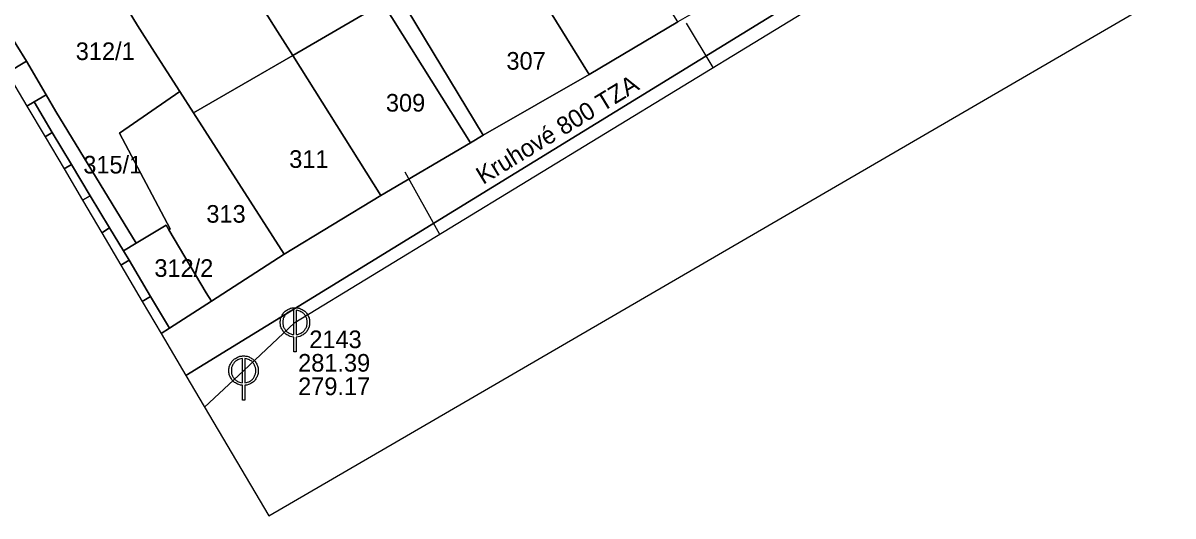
# Model space of a CAD drawing. Extents: x -571312 to -571060, y -1087128 to -1086933.
# Drawn here: x -571251.9 to -571153.9, y -1087127.5 to -1087085.5 of the extents above; entities that cross this region are included whole.
import ezdxf

# ---------------------------------------------------------------- set-up
doc = ezdxf.new("R2010")
doc.units = 0
for name, color, linetype in [('Default', 7, 'Continuous'), ('Kanalizační přípojka', 7, 'Continuous'), ('Kanalizační stoka', 7, 'Continuous'), ('Kanalizační šachta', 7, 'Continuous'), ('Parcela-polygon', 7, 'Continuous'), ('Parcela-text', 7, 'Continuous'), ('Popis kmenové stoky', 7, 'Continuous'), ('Popis šachty', 7, 'Continuous')]:
    doc.layers.add(name, color=color, linetype=linetype)

msp = doc.modelspace()

# ---------------------------------------------------------------- linework, layer by layer
at = {"layer": 'Default'}
for points in [[(-571228.863, -1087112.288), (-571229.121, -1087112.27), (-571229.383, -1087112.124), (-571229.68, -1087111.96), (-571229.845, -1087111.663), (-571230.01, -1087111.365), (-571230.01, -1087111.04), (-571230.01, -1087110.713), (-571229.842, -1087110.413), (-571229.673, -1087110.112), (-571229.375, -1087109.951), (-571229.077, -1087109.79), (-571228.76, -1087109.79), (-571228.445, -1087109.79), (-571228.146, -1087109.951), (-571227.847, -1087110.112), (-571227.678, -1087110.413), (-571227.51, -1087110.713), (-571227.51, -1087111.04), (-571227.51, -1087111.365), (-571227.675, -1087111.663), (-571227.84, -1087111.96), (-571228.137, -1087112.124), (-571228.399, -1087112.27), (-571228.657, -1087112.288)], [(-571228.863, -1087110.002), (-571229.06, -1087110.019), (-571229.275, -1087110.134), (-571229.524, -1087110.269), (-571229.663, -1087110.519), (-571229.802, -1087110.769), (-571229.802, -1087111.04), (-571229.802, -1087111.311), (-571229.666, -1087111.558), (-571229.529, -1087111.804), (-571229.28, -1087111.941), (-571229.068, -1087112.061), (-571228.863, -1087112.075)], [(-571228.657, -1087112.075), (-571228.452, -1087112.061), (-571228.238, -1087111.941), (-571227.991, -1087111.804), (-571227.854, -1087111.558), (-571227.718, -1087111.311), (-571227.718, -1087111.04), (-571227.718, -1087110.769), (-571227.858, -1087110.519), (-571227.998, -1087110.269), (-571228.247, -1087110.134), (-571228.46, -1087110.019), (-571228.657, -1087110.002)], [(-571233.243, -1087116.398), (-571233.501, -1087116.38), (-571233.763, -1087116.234), (-571234.06, -1087116.07), (-571234.225, -1087115.773), (-571234.39, -1087115.475), (-571234.39, -1087115.15), (-571234.39, -1087114.823), (-571234.222, -1087114.523), (-571234.053, -1087114.222), (-571233.755, -1087114.061), (-571233.457, -1087113.9), (-571233.14, -1087113.9), (-571232.825, -1087113.9), (-571232.526, -1087114.061), (-571232.227, -1087114.222), (-571232.058, -1087114.523), (-571231.89, -1087114.823), (-571231.89, -1087115.15), (-571231.89, -1087115.475), (-571232.055, -1087115.773), (-571232.22, -1087116.07), (-571232.517, -1087116.234), (-571232.779, -1087116.38), (-571233.037, -1087116.398)], [(-571233.243, -1087114.112), (-571233.44, -1087114.129), (-571233.655, -1087114.244), (-571233.904, -1087114.379), (-571234.043, -1087114.629), (-571234.182, -1087114.879), (-571234.182, -1087115.15), (-571234.182, -1087115.421), (-571234.046, -1087115.668), (-571233.909, -1087115.914), (-571233.66, -1087116.051), (-571233.448, -1087116.171), (-571233.243, -1087116.185)], [(-571233.037, -1087116.185), (-571232.832, -1087116.171), (-571232.618, -1087116.051), (-571232.371, -1087115.914), (-571232.234, -1087115.668), (-571232.098, -1087115.421), (-571232.098, -1087115.15), (-571232.098, -1087114.879), (-571232.238, -1087114.629), (-571232.378, -1087114.379), (-571232.627, -1087114.244), (-571232.84, -1087114.129), (-571233.037, -1087114.112)]]:
    msp.add_open_spline(points, degree=3, dxfattribs=at)
at = {"layer": 'Kanalizační přípojka'}
for points in [[(-571195.42, -1087085.56), (-571193.154, -1087089.349)], [(-571219.41, -1087098.23), (-571216.438, -1087103.534)]]:
    msp.add_lwpolyline(points, dxfattribs=at)
at = {"layer": 'Kanalizační stoka'}
for points in [[(-571228.76, -1087111.04), (-571202.29, -1087094.915), (-571175.82, -1087078.79), (-571170.61, -1087076.5)], [(-571233.14, -1087115.15), (-571228.76, -1087111.04)], [(-571236.459, -1087118.265), (-571233.14, -1087115.15)]]:
    msp.add_lwpolyline(points, dxfattribs=at)
at = {"layer": 'Kanalizační šachta'}
for points in [[(-571228.863, -1087112.075), (-571228.863, -1087110.002)], [(-571228.657, -1087110.002), (-571228.657, -1087112.075)], [(-571228.657, -1087112.288), (-571228.657, -1087113.54), (-571228.863, -1087113.54), (-571228.863, -1087112.288)], [(-571233.243, -1087116.185), (-571233.243, -1087114.112)], [(-571233.037, -1087114.112), (-571233.037, -1087116.185)], [(-571233.037, -1087116.398), (-571233.037, -1087117.65), (-571233.243, -1087117.65), (-571233.243, -1087116.398)]]:
    msp.add_lwpolyline(points, dxfattribs=at)
at = {"layer": 'Parcela-polygon'}
for p, q in [((-571253.275, -1087089.78), (-571251.598, -1087092.62)), ((-571251.598, -1087092.62), (-571250.05, -1087095.242)), ((-571250.05, -1087095.242), (-571248.437, -1087097.976)), ((-571248.437, -1087097.976), (-571246.865, -1087100.637)), ((-571246.865, -1087100.637), (-571245.233, -1087103.403)), ((-571245.233, -1087103.403), (-571243.6, -1087106.169)), ((-571243.6, -1087106.169), (-571241.775, -1087109.26)), ((-571241.775, -1087109.26), (-571240.174, -1087111.972)), ((-571240.174, -1087111.972), (-571238.048, -1087115.573))]:
    msp.add_line(p, q, dxfattribs=at)
for points in [[(-571238.048, -1087115.573), (-571084.13, -1087021.07)], [(-571100.979, -1087051.983), (-571102.73, -1087043.67), (-571081.09, -1087028.01), (-571079.74, -1087027.03), (-571084.13, -1087021.07), (-571238.048, -1087115.573)], [(-571152.72, -1087058.97), (-571161.7, -1087064.52), (-571167.4, -1087067.96), (-571170.47, -1087067.33), (-571180.9, -1087049.87), (-571182.46, -1087047.26), (-571184.97, -1087043.06), (-571189.72, -1087045.85), (-571190.56, -1087046.39), (-571185.69, -1087054.37), (-571182.17, -1087060.4), (-571174.89, -1087072.57), (-571185.7, -1087079.22), (-571194.74, -1087084.64), (-571196.13, -1087085.46), (-571203.69, -1087089.94), (-571212.71, -1087095.11), (-571213.81, -1087095.76), (-571221.44, -1087100.23), (-571229.69, -1087105.23), (-571235.88, -1087109.23), (-571239.44, -1087111.53), (-571240.174, -1087111.972)], [(-571238.048, -1087115.573), (-571230.994, -1087127.523), (-571100.979, -1087051.983)], [(-571253.275, -1087089.78), (-571251.65, -1087088.8), (-571253.39, -1087085.95), (-571254.973, -1087086.903)], [(-571251.598, -1087092.62), (-571250.99, -1087092.27), (-571249.96, -1087091.66), (-571251.65, -1087088.8), (-571253.275, -1087089.78)], [(-571250.05, -1087095.242), (-571249.45, -1087094.88), (-571250.99, -1087092.27), (-571251.598, -1087092.62)], [(-571248.437, -1087097.976), (-571247.81, -1087097.6), (-571249.45, -1087094.88), (-571250.05, -1087095.242)], [(-571246.865, -1087100.637), (-571246.22, -1087100.25), (-571247.81, -1087097.6), (-571248.437, -1087097.976)], [(-571245.233, -1087103.403), (-571244.56, -1087103), (-571246.22, -1087100.25), (-571246.865, -1087100.637)], [(-571243.6, -1087106.169), (-571242.9, -1087105.75), (-571243.38, -1087104.94), (-571244.56, -1087103), (-571245.233, -1087103.403)], [(-571241.775, -1087109.26), (-571241.06, -1087108.83), (-571242.9, -1087105.75), (-571243.6, -1087106.169)], [(-571240.174, -1087111.972), (-571239.44, -1087111.53), (-571239.96, -1087110.68), (-571241.06, -1087108.83), (-571241.775, -1087109.26)]]:
    msp.add_lwpolyline(points, dxfattribs=at)
for points in [[(-571228.73, -1087069.23), (-571237.74, -1087074.6), (-571233.74, -1087080.71), (-571230.24, -1087086.27), (-571228.95, -1087088.31), (-571221.28, -1087083.87), (-571213.81, -1087095.76), (-571212.71, -1087095.11), (-571222.73, -1087078.55), (-571224.67, -1087075.35)], [(-571205.73, -1087074.32), (-571209.1, -1087076.39), (-571208.46, -1087077.42), (-571210.64, -1087078.7), (-571210.13, -1087079.52), (-571203.69, -1087089.94), (-571196.13, -1087085.46), (-571200.02, -1087079.25), (-571204.26, -1087072.46), (-571206.54, -1087072.99)], [(-571230.24, -1087086.27), (-571233.74, -1087080.71), (-571237.74, -1087074.6), (-571245.94, -1087079.58), (-571242.19, -1087085.75), (-571240.73, -1087088.03), (-571238.58, -1087091.38), (-571237.41, -1087093.2), (-571228.95, -1087088.31)], [(-571203.69, -1087089.94), (-571210.13, -1087079.52), (-571210.53, -1087081.27), (-571213.1, -1087082.94), (-571214.96, -1087082.48), (-571218.81, -1087076.21), (-571222.73, -1087078.55), (-571212.71, -1087095.11)], [(-571254.21, -1087084.57), (-571253.39, -1087085.95), (-571251.65, -1087088.8), (-571249.96, -1087091.66), (-571249.14, -1087093.07), (-571242.3, -1087104.3), (-571239.74, -1087102.77), (-571239.52, -1087103.15), (-571239.41, -1087103.08), (-571243.72, -1087094.92), (-571238.58, -1087091.38), (-571240.73, -1087088.03), (-571242.19, -1087085.75), (-571245.94, -1087079.58)], [(-571228.95, -1087088.31), (-571221.44, -1087100.23), (-571213.81, -1087095.76), (-571221.28, -1087083.87)], [(-571228.95, -1087088.31), (-571237.41, -1087093.2), (-571229.69, -1087105.23), (-571221.44, -1087100.23)], [(-571249.96, -1087091.66), (-571250.99, -1087092.27), (-571249.45, -1087094.88), (-571247.81, -1087097.6), (-571246.22, -1087100.25), (-571244.56, -1087103), (-571243.38, -1087104.94), (-571242.3, -1087104.3), (-571249.14, -1087093.07)], [(-571238.58, -1087091.38), (-571243.72, -1087094.92), (-571239.41, -1087103.08), (-571239.52, -1087103.15), (-571236.32, -1087108.51), (-571235.88, -1087109.23), (-571229.69, -1087105.23), (-571237.41, -1087093.2)], [(-571243.38, -1087104.94), (-571242.9, -1087105.75), (-571241.06, -1087108.83), (-571239.96, -1087110.68), (-571239.44, -1087111.53), (-571235.88, -1087109.23), (-571236.32, -1087108.51), (-571239.52, -1087103.15), (-571239.74, -1087102.77), (-571242.3, -1087104.3)]]:
    msp.add_lwpolyline(points, close=True, dxfattribs=at)

# ---------------------------------------------------------------- texts
at = {"layer": 'Parcela-text'}
for s, p in [('312/1', (-571247.44, -1087088.7)), ('307', (-571210.74, -1087089.52)), ('309', (-571221.01, -1087093.09)), ('315/1', (-571246.8, -1087098.36)), ('311', (-571229.25, -1087097.88)), ('313', (-571236.31, -1087102.55)), ('312/2', (-571240.74, -1087107.16))]:
    msp.add_text(s, height=1.5, dxfattribs=at).set_placement(p)
at = {"layer": 'Popis kmenové stoky'}
msp.add_text('Kruhové 800 TZA', height=1.5, rotation=31.34895, dxfattribs=at).set_placement((-571212.733, -1087099.34))
at = {"layer": 'Popis šachty'}
for s, p in [('2143', (-571227.539, -1087113.231)), ('281.39', (-571228.489, -1087115.231)), ('279.17', (-571228.489, -1087117.231))]:
    msp.add_text(s, height=1.5, dxfattribs=at).set_placement(p)

doc.saveas('drawing.dxf')
